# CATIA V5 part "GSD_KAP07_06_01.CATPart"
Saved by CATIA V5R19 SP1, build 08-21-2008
Part number: GSD_SPLIT_01
Definition: Beispielmodell für die Funktion Trimmen / Split
Description: CATIA V5 Flächenmodellierung  Copyright (c) 2009 Maik Hertha IT Consultants
Bounding box of the stored display mesh (mm): x -25.001 to 38.492, y -17.514 to 55.49, z 4.919 to 33.415
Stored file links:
  \GSD_BUCH_UEBUNG\GSD_KAP07_06_01.CATPart
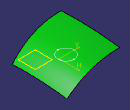
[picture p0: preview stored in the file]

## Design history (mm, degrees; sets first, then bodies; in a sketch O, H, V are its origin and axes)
AxisSystem1 "Absolute Axis System": origin (0, 0, 0), X (1, 0, 0), Y (0, 1, 0), Z (0, 0, 1)
Set1 "Split Support"
  Plane1: type Equation, A 0, B 1, C 0, Length 20
  Point1: type OnPlane, Support Plane1, Direction (-1, 0, 0), H -15, V 15
Set2
  Sketch1 on Plane1, origin (15, 20, 15), H (-1, 0, 0), V (0, 0, 1)
    spline S1 through (-23.4922, -6.9379) (4.2802, 11.5546) (40.0009, 17.999)
    curve C1
  Plane2: type Equation, A 1, B 0, C 0, Length -20
  Sketch2 on Plane2, origin (-20, 20, 15), H (0, 1, 0), V (0, 0, 1)
    spline S1 through (-36.5228, 7.5812) (-0.9757, 7.6534) (34.5484, 4.4061)
    curve C1
  Sweep1: type Unspec, Guide Sketch2.C1, Profile Sketch1.C1
Set3
  Plane3: type Equation, A 0, B 0, C 1, Length 20
  Sketch3 on Plane3, origin (15, 20, 20), H (0, 1, 0), V (-1, 0, 0)
    circle A1 centre (-0.2271, 8.7974) radius 10
    radius A1 = 10
Body1 (main body)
